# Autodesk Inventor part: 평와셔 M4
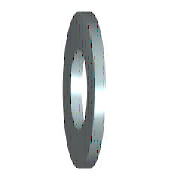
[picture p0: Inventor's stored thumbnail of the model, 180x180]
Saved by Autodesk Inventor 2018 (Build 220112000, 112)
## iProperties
IsCustomPart: 1
Created: 2012-02
Part Number: 평와셔 M4
Material: 스테인리스강
Description: 평면 와셔 - 일반 시리즈 - 제품 등급 A
Document SubType Name: Modeling
Standard: ISO 7089
Designer: mdu-01
Standard Revision: Second edition 2000-06-01
Standards Organization: ISO
Language: ko-KR
Size Designation: 4 - 140 HV
Categories: <MemberInstance><Categories><Category DisplayName="조임쇠" InternalName="e4da775c-781d-43d5-af7c-5136215cf5a6" Mnemonic="FSTN"><Category DisplayName="와셔" InternalN
Density: 8.08 g/cm^3
Appearance: 반광택
Author: mdu-01
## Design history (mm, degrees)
sketch "스케치"
  geometry: C1 r 4.5 at (0, 0); C2 r 2.15 at (0, 0); 1 further point
  constraints: 2 centre point, 2 coincident
  dimensions: "d0" = 4.3 diameter of C2 (= SD1); "d1" = 9 diameter of C1 (= SD2)
extrude "본체" new body sketch "스케치" distance "d2" = 0.8 (= SD); taper "d3" = 0 deg
workaxis "Work Axis1"
workplane "Work Plane1"
body "Solid1"
other parameters: "SD1" = 4.3 [user parameter; used in 1 equation term], "SD2" = 9 [user parameter; used in 1 equation term], "SD" = 0.8 [user parameter; used in 1 equation term], "d4" = 0, "d5" = 0, "d6" = 0, "d7" = 0, "NND" = 4 [user parameter]
